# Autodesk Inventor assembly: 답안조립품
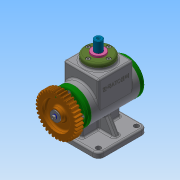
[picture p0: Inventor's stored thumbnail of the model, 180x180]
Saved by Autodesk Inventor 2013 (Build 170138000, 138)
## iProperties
Created: 2019-01
Part Number: 답안조립품
Document SubType Name: Assembly
Designer: Gpr
Author: Gpr
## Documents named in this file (18)
- C:\Users\Administrator\Desktop\390107V1047\답안조립품.iam
- C:\Users\Administrator\Desktop\390107V1047\본체.ipt
- C:\Users\Administrator\Desktop\390107V1047\뒤커버.ipt
- C:\Users\Administrator\Desktop\390107V1047\베어링 6203.ipt
- C:\Users\Administrator\Desktop\390107V1047\볼트 M4.ipt
- C:\Users\Administrator\Desktop\390107V1047\스퍼기어.ipt
- C:\Users\Administrator\Desktop\390107V1047\스프링와셔.ipt
- C:\Users\Administrator\Desktop\390107V1047\앞커버.ipt
- C:\Users\Administrator\Desktop\390107V1047\오일 실 17 30 5.ipt
- C:\Users\Administrator\Desktop\390107V1047\키 4x4x12.ipt
- C:\Users\Administrator\Desktop\390107V1047\편심축.ipt
- C:\Users\Administrator\Desktop\390107V1047\평와셔.ipt
- C:\Users\Administrator\Desktop\390107V1047\멈춤링.ipt
- C:\Users\Administrator\Desktop\390107V1047\부시.ipt
- C:\Users\Administrator\Desktop\390107V1047\상부커버.ipt
- C:\Users\Administrator\Desktop\390107V1047\스프링조립용 와셔.ipt
- C:\Users\Administrator\Desktop\390107V1047\슬라이더.ipt
- C:\Users\Administrator\Desktop\390107V1047\가변스프링.ipt
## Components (1 placed, 1 different names)
1. 가변스프링:1
